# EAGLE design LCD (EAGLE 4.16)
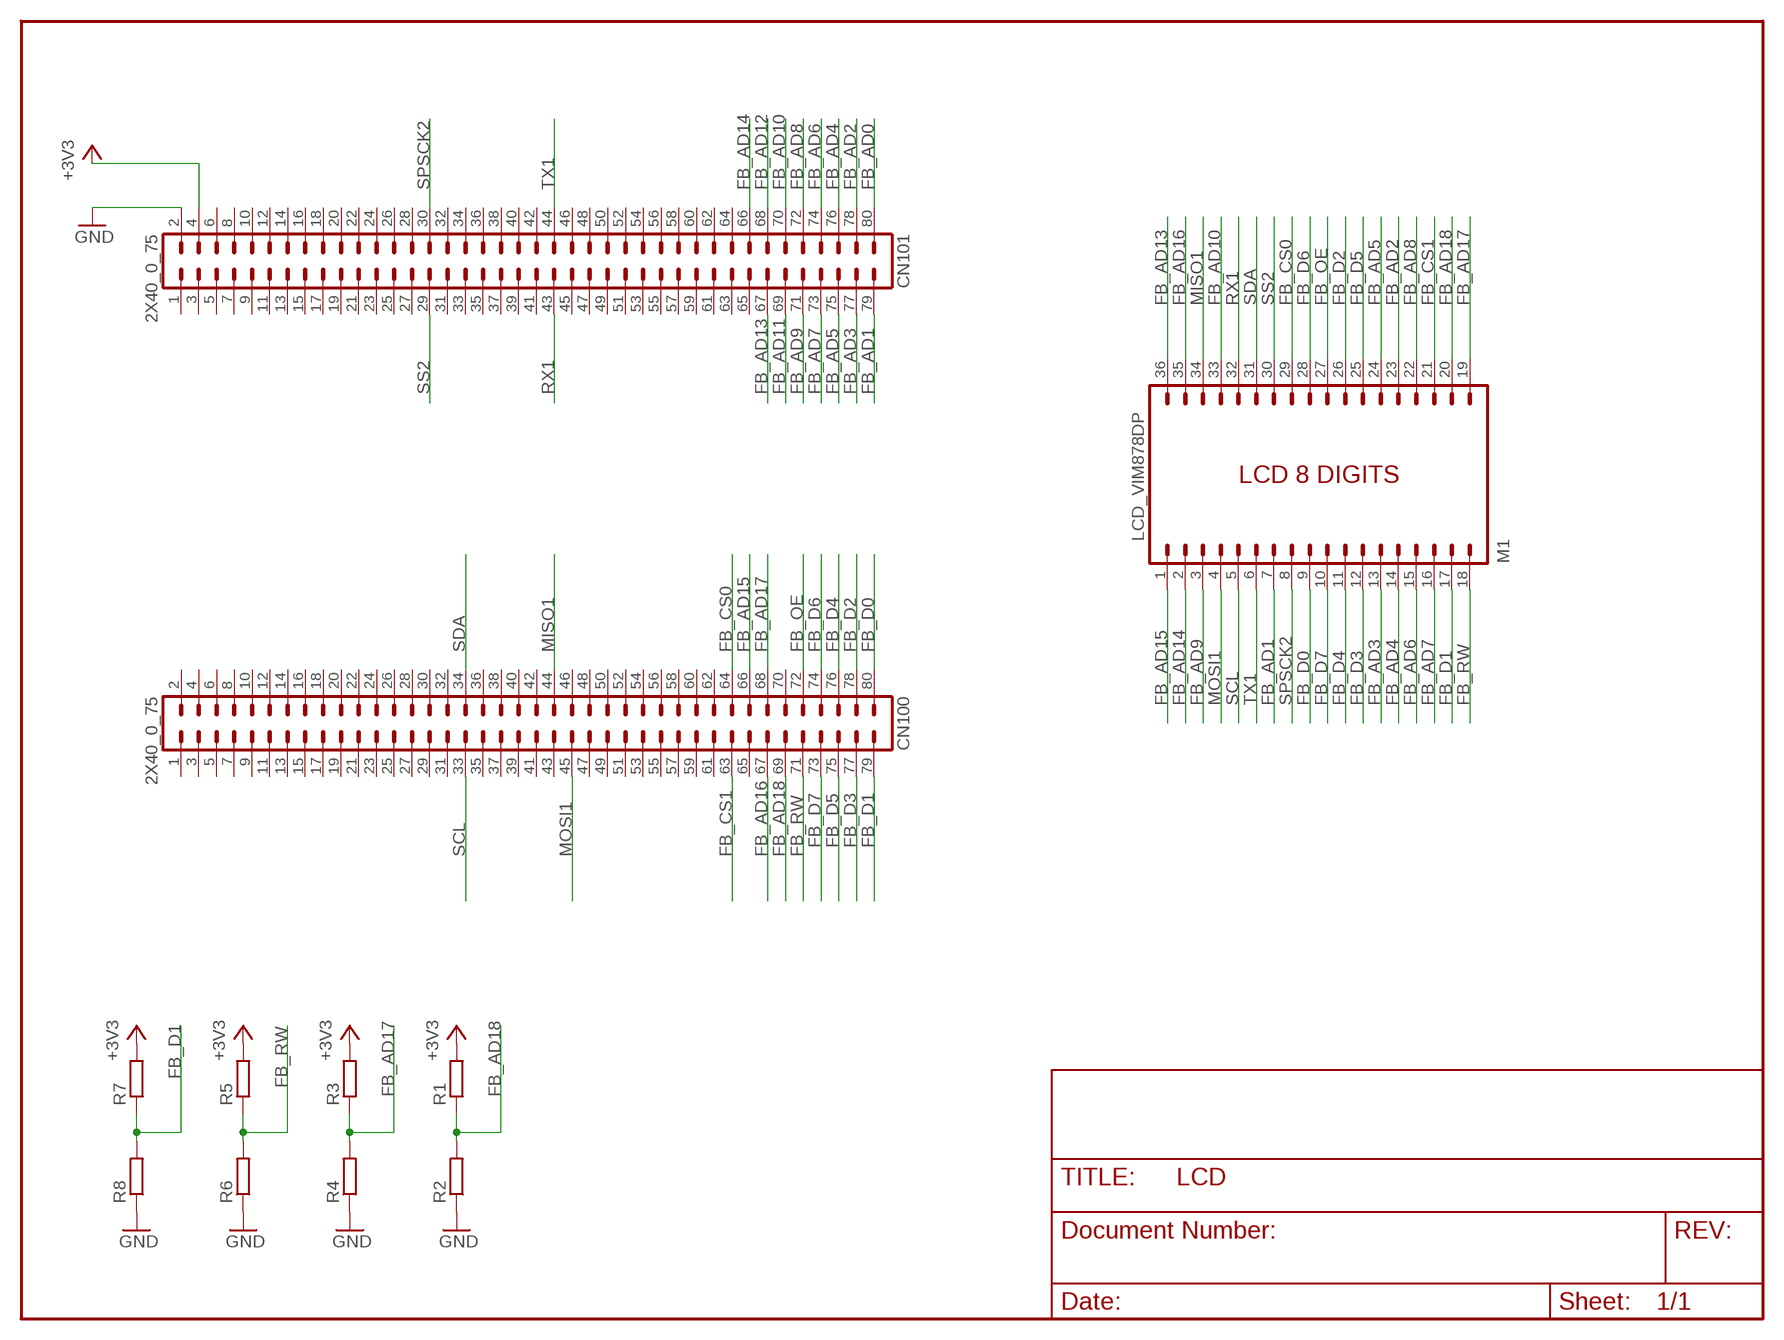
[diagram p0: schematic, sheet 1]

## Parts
CN100  2X40_0_75  [CON_2X40_0_75]
CN101  2X40_0_75  [CON_2X40_0_75]
M1  LCD_VIM878DP  [LCD_2X18]
R1  R-EU_0207/10  [0207/10]
R2  R-EU_0207/10  [0207/10]
R3  R-EU_0207/10  [0207/10]
R4  R-EU_0207/10  [0207/10]
R5  R-EU_0207/10  [0207/10]
R6  R-EU_0207/10  [0207/10]
R7  R-EU_0207/10  [0207/10]
R8  R-EU_0207/10  [0207/10]

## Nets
+3V3: CN101.4 R1.2 R3.2 R5.2 R7.2
FB_AD0: CN101.80
FB_AD1: CN101.79 M1.7
FB_AD2: CN101.78 M1.23
FB_AD3: CN101.77 M1.13
FB_AD4: CN101.76 M1.14
FB_AD5: CN101.75 M1.24
FB_AD6: CN101.74 M1.15
FB_AD7: CN101.73 M1.16
FB_AD8: CN101.72 M1.22
FB_AD9: CN101.71 M1.3
FB_AD10: CN101.70 M1.33
FB_AD11: CN101.69
FB_AD12: CN101.68
FB_AD13: CN101.67 M1.36
FB_AD14: CN101.66 M1.2
FB_AD15: CN100.66 M1.1
FB_AD16: CN100.67 M1.35
FB_AD17: CN100.68 M1.19 R3.1 R4.2
FB_AD18: CN100.69 M1.20 R1.1 R2.2
FB_CS0: CN100.64 M1.29
FB_CS1: CN100.63 M1.21
FB_D0: CN100.80 M1.9
FB_D1: CN100.79 M1.17 R7.1 R8.2
FB_D2: CN100.78 M1.26
FB_D3: CN100.77 M1.12
FB_D4: CN100.76 M1.11
FB_D5: CN100.75 M1.25
FB_D6: CN100.74 M1.28
FB_D7: CN100.73 M1.10
FB_OE: CN100.72 M1.27
FB_RW: CN100.71 M1.18 R5.1 R6.2
GND: CN101.2 R2.1 R4.1 R6.1 R8.1
MISO1: CN100.44 M1.34
MOSI1: CN100.45 M1.4
RX1: CN101.43 M1.32
SCL: CN100.33 M1.5
SDA: CN100.34 M1.31
SPSCK2: CN101.30 M1.8
SS2: CN101.29 M1.30
TX1: CN101.44 M1.6
Unconnected: CN100.1 CN100.2 CN100.3 CN100.4 CN100.5 CN100.6 CN100.7 CN100.8 CN100.9 CN100.10 CN100.11 CN100.12 CN100.13 CN100.14 CN100.15 CN100.16 CN100.17 CN100.18 CN100.19 CN100.20 CN100.21 CN100.22 CN100.23 CN100.24 CN100.25 CN100.26 CN100.27 CN100.28 CN100.29 CN100.30 CN100.31 CN100.32 CN100.35 CN100.36 CN100.37 CN100.38 CN100.39 CN100.40 CN100.41 CN100.42 CN100.43 CN100.46 CN100.47 CN100.48 CN100.49 CN100.50 CN100.51 CN100.52 CN100.53 CN100.54 CN100.55 CN100.56 CN100.57 CN100.58 CN100.59 CN100.60 CN100.61 CN100.62 CN100.65 CN100.70 CN101.1 CN101.3 CN101.5 CN101.6 CN101.7 CN101.8 CN101.9 CN101.10 CN101.11 CN101.12 CN101.13 CN101.14 CN101.15 CN101.16 CN101.17 CN101.18 CN101.19 CN101.20 CN101.21 CN101.22 CN101.23 CN101.24 CN101.25 CN101.26 CN101.27 CN101.28 CN101.31 CN101.32 CN101.33 CN101.34 CN101.35 CN101.36 CN101.37 CN101.38 CN101.39 CN101.40 CN101.41 CN101.42 CN101.45 CN101.46 CN101.47 CN101.48 CN101.49 CN101.50 CN101.51 CN101.52 CN101.53 CN101.54 CN101.55 CN101.56 CN101.57 CN101.58 CN101.59 CN101.60 CN101.61 CN101.62 CN101.63 CN101.64 CN101.65

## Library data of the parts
CN100 CN101 = Prac1:2X40_0_75
M1 = Prac1:LCD_VIM878DP
R1-R8 = rcl:R-EU_: RESISTOR, European symbol

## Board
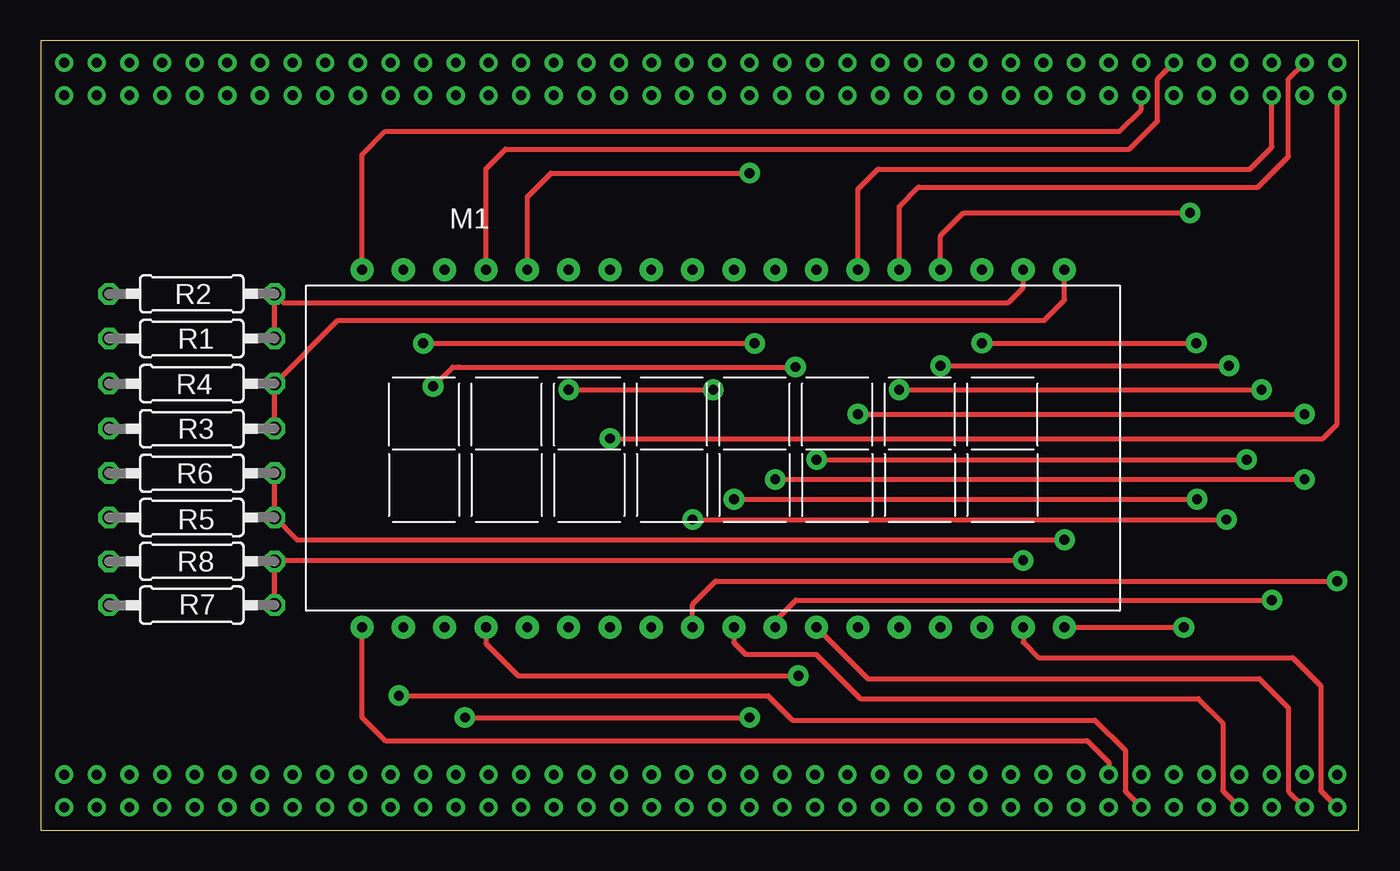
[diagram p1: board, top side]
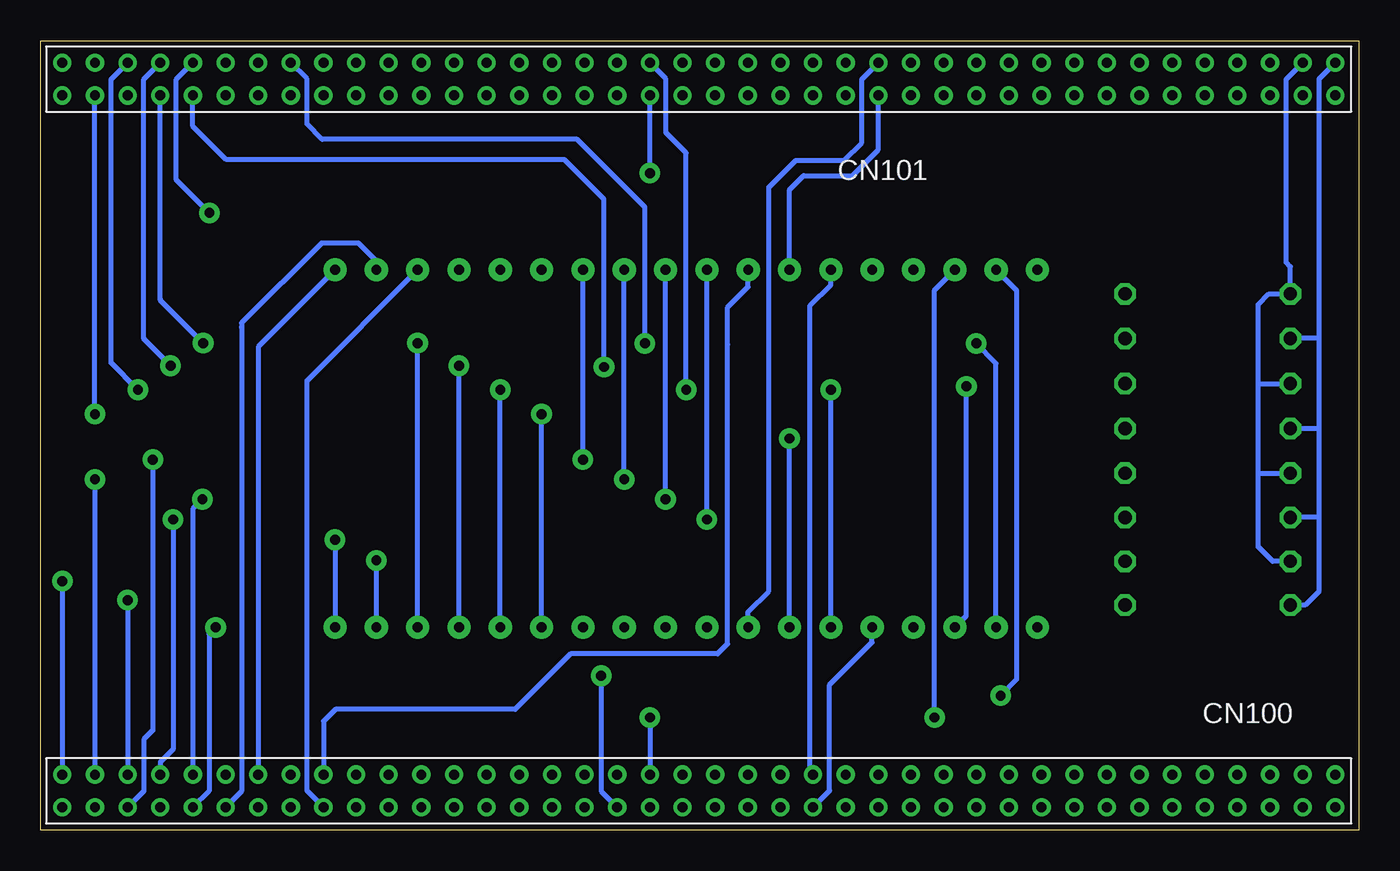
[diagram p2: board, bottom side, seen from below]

Size 81.03 x 48.51 mm. Coordinates in mm from the lower left corner, seen from the top.
Outline: 0,0 81.03,0 81.03,48.51 0,48.51 0,0
Copper layers (1*16): Top 0.035mm / dielectric 1.5mm / Bottom 0.035mm
Design rules "default": minimum track width 10mil, minimum drill 24mil, track to track 8mil, track to pad 8mil, pad to pad 8mil, via to via 8mil, smd to smd 8mil, copper to edge 40mil, drill to drill 8mil, minimum pad ring 10mil, minimum via ring 8mil, stop-mask expansion 4mil, vias tented up to drill 0mil, thermal gap 10mil

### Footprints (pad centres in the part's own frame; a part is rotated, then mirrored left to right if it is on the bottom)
CON_2X40_0_75 = drill 0.61 pad 1.016 round: 1 0,0; 2 0,-2.007; 3 2.007,0; 4 2.007,-2.007; 5 4.013,0; 6 4.013,-2.007; 7 6.02,0; 8 6.02,-2.007; 9 8.026,0; 10 8.026,-2.007; 11 10.033,0; 12 10.033,-2.007; 13 12.04,0; 14 12.04,-2.007; 15 14.046,0; 16 14.046,-2.007; 17 16.053,0; 18 16.053,-2.007; 19 18.059,0; 20 18.059,-2.007; 21 20.066,0; 22 20.066,-2.007; 23 22.073,0; 24 22.073,-2.007; 25 24.079,0; 26 24.079,-2.007; 27 26.086,0; 28 26.086,-2.007; 29 28.092,0; 30 28.092,-2.007; 31 30.099,0; 32 30.099,-2.007; 33 32.106,0; 34 32.106,-2.007; 35 34.112,0; 36 34.112,-2.007; 37 36.119,0; 38 36.119,-2.007; 39 38.125,0; 40 38.125,-2.007; 41 40.132,0; 42 40.132,-2.007; 43 42.139,0; 44 42.139,-2.007; 45 44.145,0; 46 44.145,-2.007; 47 46.152,0; 48 46.152,-2.007; 49 48.158,0; 50 48.158,-2.007; 51 50.165,0; 52 50.165,-2.007; 53 52.172,0; 54 52.172,-2.007; 55 54.178,0; 56 54.178,-2.007; 57 56.185,0; 58 56.185,-2.007; 59 58.191,0; 60 58.191,-2.007; 61 60.198,0; 62 60.198,-2.007; 63 62.205,0; 64 62.205,-2.007; 65 64.211,0; 66 64.211,-2.007; 67 66.218,0; 68 66.218,-2.007; 69 68.224,0; 70 68.224,-2.007; 71 70.231,0; 72 70.231,-2.007; 73 72.238,0; 74 72.238,-2.007; 75 74.244,0; 76 74.244,-2.007; 77 76.251,0; 78 76.251,-2.007; 79 78.257,0; 80 78.257,-2.007
LCD_2X18 = drill 0.61 pad 1.422 round: 1 3.429,-1.016; 2 5.969,-1.016; 3 8.509,-1.016; 4 11.049,-1.016; 5 13.589,-1.016; 6 16.129,-1.016; 7 18.669,-1.016; 8 21.209,-1.016; 9 23.749,-1.016; 10 26.289,-1.016; 11 28.829,-1.016; 12 31.369,-1.016; 13 33.909,-1.016; 14 36.449,-1.016; 15 38.989,-1.016; 16 41.529,-1.016; 17 44.069,-1.016; 18 46.609,-1.016; 19 46.609,20.955; 20 44.069,20.955; 21 41.529,20.955; 22 38.989,20.955; 23 36.449,20.955; 24 33.909,20.955; 25 31.369,20.955; 26 28.829,20.955; 27 26.289,20.955; 28 23.749,20.955; 29 21.209,20.955; 30 18.669,20.955; 31 16.129,20.955; 32 13.589,20.955; 33 11.049,20.955; 34 8.509,20.955; 35 5.969,20.955; 36 3.429,20.955
0207/10 = drill 0.813 octagon: 1 -5.08,0; 2 5.08,0

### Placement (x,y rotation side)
CN100  1.44,1.41 180 bottom
CN101  1.44,45.15 180 bottom
M1  16.33,13.47 0 top
R1  9.29,32.96 180 top
R2  9.29,30.21 0 top
R3  9.29,27.44 180 top
R4  9.29,24.68 0 top
R5  9.29,21.93 180 top
R6  9.29,19.22 0 top
R7  9.29,16.52 180 top
R8  9.29,13.83 0 top

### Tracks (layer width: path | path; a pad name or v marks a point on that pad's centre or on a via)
+3V3
  Bottom 0.305: CN101.4 4.47,46.14 4.47,34.89 4.21,34.63 R1.2 5.53,32.96 6.19,32.3 6.19,27.44 | 6.19,21.93 6.19,17.41 5.3,16.52 R7.2 | 6.19,21.93 6.19,27.44 | 6.19,21.93 R5.2 | 6.19,27.44 R3.2
FB_AD1  (via drill 0.61 pad 1.27)
  Top 0.305: CN101.79 79.7,24.96 78.81,24.07 v35,24.07
  Bottom 0.305: M1.7 v35,24.07
FB_AD2
  Top 0.305: M1.23 52.78,38.32 53.97,39.51 74.82,39.51 76.7,41.39 76.7,46.16 CN101.78
FB_AD3  (via drill 0.61 pad 1.27)
  Top 0.305: v50.24,25.56 v77.69,25.56
  Bottom 0.305: v77.69,25.56 CN101.77 | M1.13 v50.24,25.56
FB_AD4  (via drill 0.61 pad 1.27)
  Top 0.305: v52.78,27.06 v75.05,27.06
  Bottom 0.305: CN101.76 76.7,46.14 76.7,28.84 76.7,28.71 v75.05,27.06 | M1.14 v52.78,27.06
FB_AD5
  Top 0.305: M1.24 50.24,39.38 51.48,40.63 74.34,40.63 75.69,41.97 CN101.75
FB_AD6  (via drill 0.61 pad 1.27)
  Top 0.305: v55.32,28.54 v73.05,28.54
  Bottom 0.305: CN101.74 74.7,46.14 74.7,30.24 74.7,30.19 v73.05,28.54 | M1.15 v55.32,28.54
FB_AD7  (via drill 0.61 pad 1.27)
  Top 0.305: v57.86,29.93 v71.04,29.93
  Bottom 0.305: CN101.73 73.68,32.65 73.68,32.58 v71.04,29.93 | M1.16 v57.86,29.93
FB_AD8  (via drill 0.61 pad 1.27)
  Top 0.305: M1.22 55.32,36.51 56.74,37.93 v70.66,37.93
  Bottom 0.305: CN101.72 72.69,46.14 72.69,39.97 v70.66,37.93
FB_AD9  (via drill 0.61 pad 1.27)
  Top 0.305: 25.73,28.46 25.65,28.46 | 25.73,28.46 v46.4,28.46 | v24.13,27.27 25.32,28.46 25.73,28.46
  Bottom 0.305: CN101.71 71.67,43.27 69.62,41.21 48.84,41.21 46.4,38.77 v46.4,28.46 | M1.3 24.13,13.17 v24.13,27.27
FB_AD10
  Top 0.305: M1.33 27.38,40.65 28.57,41.85 66.92,41.85 68.65,43.57 68.65,46.14 CN101.70
FB_AD13
  Top 0.305: M1.36 19.76,41.52 21.18,42.94 66.31,42.94 67.66,44.28 CN101.67
FB_AD14  (via drill 0.61 pad 1.27)
  Top 0.305: v23.52,29.91 v43.89,29.91
  Bottom 0.305: CN101.66 64.66,46.16 64.66,43.4 63.72,42.46 48.05,42.46 43.89,38.29 v43.89,29.91 | v23.52,29.91 22.3,28.69 M1.2
FB_AD15
  Top 0.305: M1.1 19.76,6.92 21.18,5.5 64.33,5.5 65.65,4.18 CN100.66
FB_AD16  (via drill 0.61 pad 1.27)
  Top 0.305: CN100.67 66.67,2.4 66.67,4.91 64.82,6.77 46.22,6.77 44.72,8.27 v22.02,8.27
  Bottom 0.305: M1.35 21.03,33.16 21.03,9.26 v22.02,8.27
FB_AD17
  Top 0.305: R4.2 R3.1 18.26,31.33 61.69,31.33 62.94,32.58 M1.19
  Bottom 0.305: CN100.68 67.66,29.71 M1.19
FB_AD18
  Top 0.305: R2.2 R1.1 14.9,32.42 59.48,32.42 60.4,33.34 M1.20
  Bottom 0.305: CN100.69 68.68,2.4 68.68,30.9 | M1.20 60.4,34.99 61.49,36.08 63.77,36.08 68.68,31.18 68.68,30.9 | 68.68,30.9 68.68,30.92
FB_CS0
  Bottom 0.305: CN100.64 63.65,6.69 62.91,7.43 51.86,7.43 48.46,10.83 39.42,10.83 38.81,11.44 38.81,29.83 | M1.29 37.54,33.39 38.81,32.12 38.81,29.83 | 38.81,29.83 38.81,29.86
FB_CS1
  Bottom 0.305: CN100.63 64.66,2.43 64.66,27.62 M1.21
FB_D0  (via drill 0.61 pad 1.27)
  Top 0.305: M1.9 40.08,13.88 41.5,15.3 v79.7,15.3
  Bottom 0.305: v79.7,15.3 CN100.80
FB_D1  (via drill 0.61 pad 1.27)
  Top 0.305: M1.17 60.4,11.54 61.34,10.6 76.96,10.6 78.68,8.88 78.68,2.43 CN100.79 | R8.2 R7.1 14.42,16.57 v60.4,16.57
  Bottom 0.305: v60.4,16.57 M1.17
FB_D2  (via drill 0.61 pad 1.27)
  Top 0.305: v45.16,21.55 v77.69,21.55
  Bottom 0.305: v45.16,21.55 M1.26 | v77.69,21.55 CN100.78
FB_D3
  Top 0.305: M1.12 50.85,9.31 74.93,9.31 76.7,7.53 76.7,2.4 CN100.77
FB_D4  (via drill 0.61 pad 1.27)
  Top 0.305: M1.11 45.16,12.86 46.43,14.13 v75.69,14.13
  Bottom 0.305: v75.69,14.13 CN100.76
FB_D5  (via drill 0.61 pad 1.27)
  Top 0.305: v47.7,22.77 v74.14,22.77
  Bottom 0.305: CN100.75 74.7,2.4 74.7,5.58 74.14,6.13 v74.14,22.77 | v47.7,22.77 M1.25
FB_D6  (via drill 0.61 pad 1.27)
  Top 0.305: v40.08,19.09 v72.89,19.09
  Bottom 0.305: v40.08,19.09 M1.28 | v72.89,19.09 72.89,4.97 73.68,4.18 CN100.74
FB_D7
  Top 0.305: M1.10 42.62,11.52 43.33,10.81 47.67,10.81 50.39,8.09 71.17,8.09 72.66,6.59 72.66,2.43 CN100.73
FB_OE  (via drill 0.61 pad 1.27)
  Top 0.305: v42.62,20.33 v71.09,20.33
  Bottom 0.305: v42.62,20.33 M1.27 | v71.09,20.33 71.67,19.75 CN100.72
FB_RW  (via drill 0.61 pad 1.27)
  Top 0.305: M1.18 v70.28,12.46 | R5.1 R6.2 15.74,17.84 v62.94,17.84
  Bottom 0.305: CN100.71 70.68,2.4 70.68,12.05 v70.28,12.46 | v62.94,17.84 M1.18
GND
  Bottom 0.305: CN101.2 2.43,46.16 2.43,30.21 | 2.43,19.21 2.43,14.69 3.3,13.83 R8.1 | 2.43,19.21 2.43,24.68 | 2.43,24.68 2.43,30.21 | 2.43,19.21 R6.1 | 2.43,24.68 R4.1 | 2.43,30.21 R2.1
MISO1  (via drill 0.61 pad 1.27)
  Top 0.305: v26.08,6.92 v43.58,6.92
  Bottom 0.305: M1.34 26.08,33.18 v26.08,6.92 | v43.58,6.92 CN100.44
MOSI1  (via drill 0.61 pad 1.27)
  Top 0.305: M1.4 27.38,11.47 29.36,9.49 v46.58,9.49
  Bottom 0.305: CN100.45 46.58,2.4 v46.58,9.49
RX1  (via drill 0.61 pad 1.27)
  Top 0.305: M1.32 29.92,38.93 31.36,40.37 v43.58,40.37
  Bottom 0.305: v43.58,40.37 CN101.43
SCL
  Bottom 0.305: CN100.33 32.53,2.43 32.53,8.93 29.92,11.54 M1.5
SDA
  Bottom 0.305: M1.31 32.46,33.52 33.73,32.25 33.73,3.59 CN100.34
SPSCK2
  Bottom 0.305: CN101.30 30.55,46.14 30.55,42.25 31.64,41.16 34.62,41.16 36.27,39.51 36.27,14.69 37.54,13.42 M1.8
SS2
  Bottom 0.305: CN101.29 29.54,41.82 31.14,40.22 34.13,40.22 35,39.36 M1.30
TX1  (via drill 0.61 pad 1.27)
  Top 0.305: v32.46,27.06 v41.35,27.06
  Bottom 0.305: CN101.44 42.59,46.16 42.59,42.86 41.35,41.62 v41.35,27.06 | M1.6 v32.46,27.06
